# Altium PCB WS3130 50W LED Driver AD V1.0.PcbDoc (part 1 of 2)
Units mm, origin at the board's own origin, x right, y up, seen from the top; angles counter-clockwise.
Board outline 122.48 x 39.96 mm, 2 copper layers (Top Layer, Bottom Layer); 58 components, 32 nets, 164 pads, 32 vias.
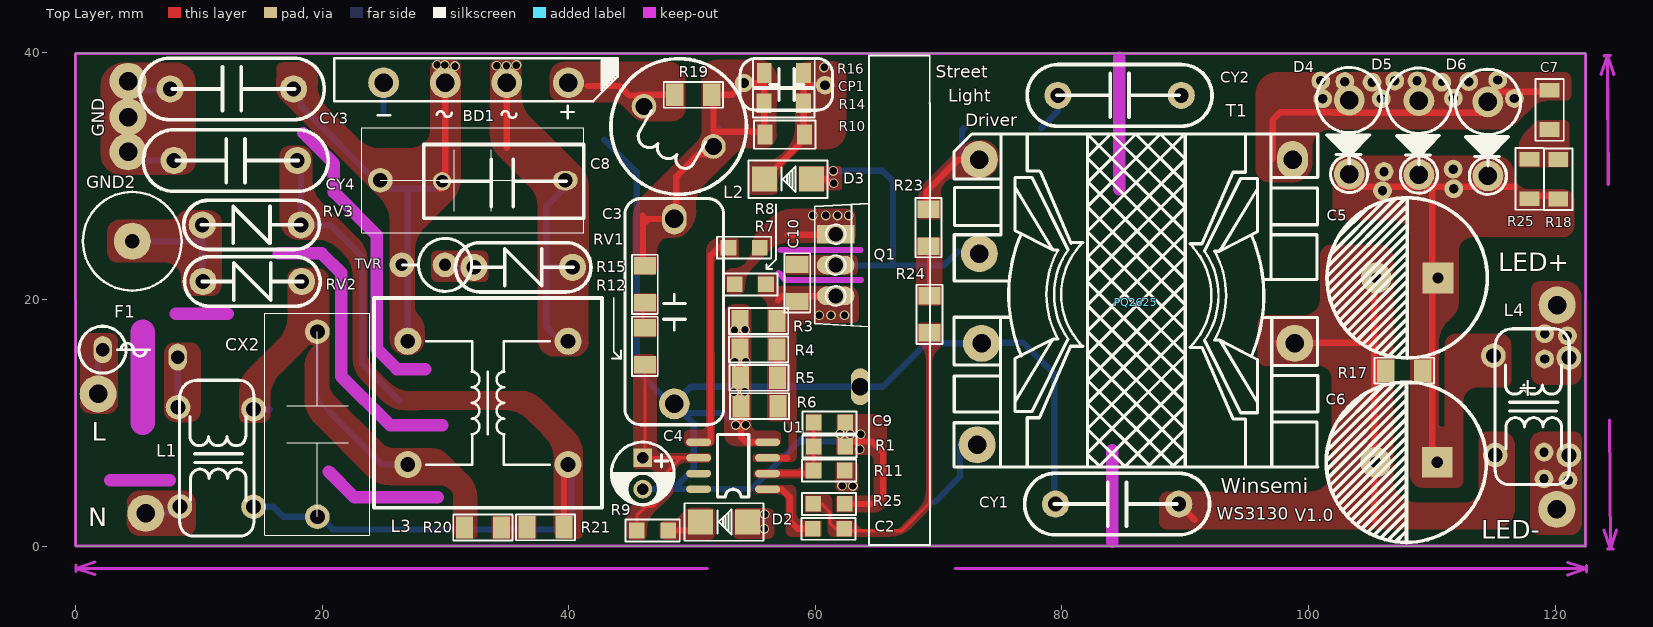
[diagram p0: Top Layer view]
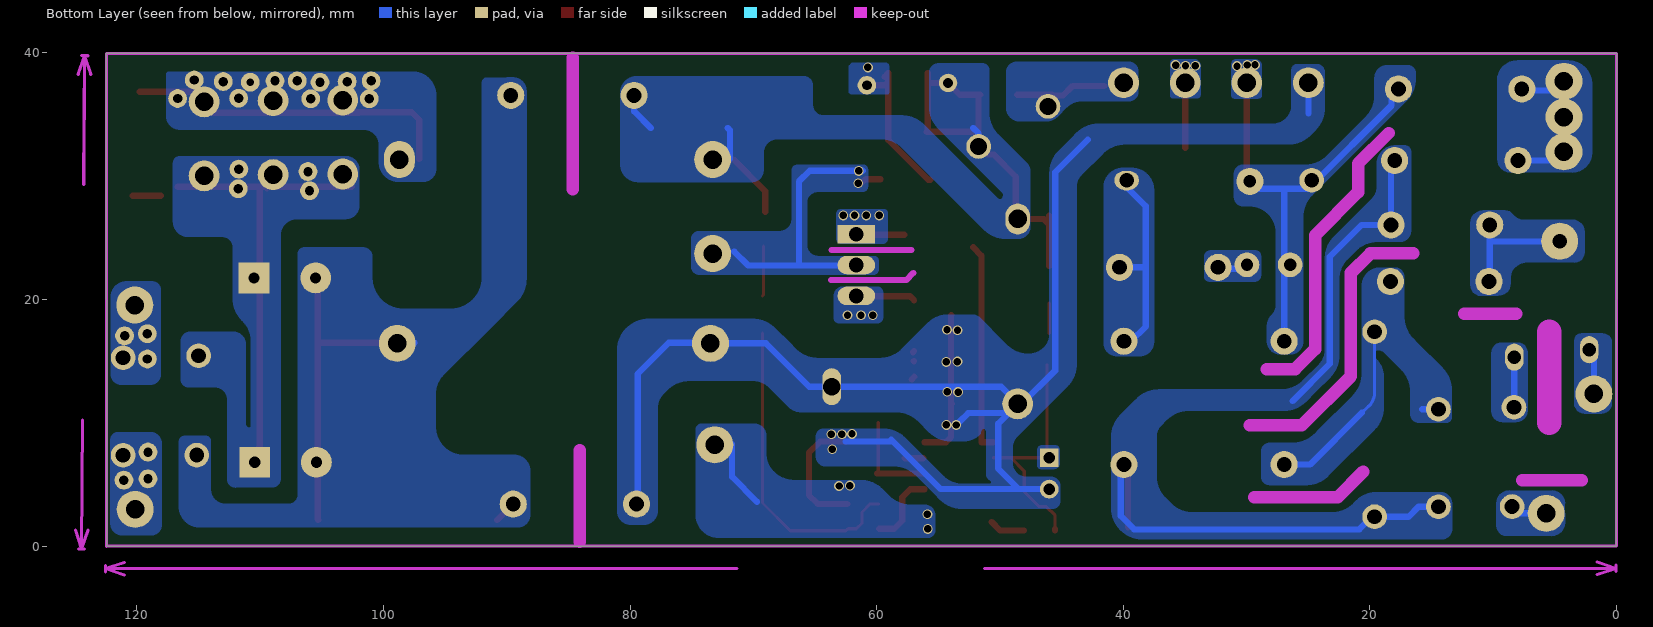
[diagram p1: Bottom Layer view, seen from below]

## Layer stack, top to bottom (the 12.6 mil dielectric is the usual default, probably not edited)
Top Layer: signal copper 0.0356
Dielectric: dielectric 0.32, FR-4, Dk 4.8
Bottom Layer: signal copper 0.0356

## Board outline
-0.011,39.954 0,0 122.439,0 122.472,39.96 -0.011,39.954

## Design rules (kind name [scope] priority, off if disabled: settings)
AcuteAngle [All] p1: minimum=1.50000000000000E+0001
Clearance Clearance_1 [All] p1 off: gap=0.254
Clearance [All] p2 off: gap=0.05
FanoutControl Fanout_Small [All] p1 off: bgadir=Out bgaviamode=Centered fanoutstyle=Auto fanoutdirection=Alternating viagrid=0.025 // Protel DXP Scope 1 Expression Was: (CompPinCount < 5)   Fanout_Small (Default Rule)
FanoutControl Fanout_Default [All] p2: bgadir=Out bgaviamode=Centered fanoutstyle=Auto fanoutdirection=Alternating viagrid=0.025 // Fanout_Default (Default Rule)
FanoutControl Fanout_SOIC [All] p3 off: bgadir=Out bgaviamode=Centered fanoutstyle=Auto fanoutdirection=Alternating viagrid=0.025 // Protel DXP Scope 1 Expression Was: IsSOIC   Fanout_SOIC (Default Rule)
FanoutControl Fanout_BGA [All] p4 off: bgadir=Out bgaviamode=Centered fanoutstyle=Auto fanoutdirection=Alternating viagrid=0.025 // Protel DXP Scope 1 Expression Was: IsBGA   Fanout_BGA (Default Rule)
FanoutControl Fanout_LCC [All] p5 off: bgadir=Out bgaviamode=Centered fanoutstyle=Auto fanoutdirection=Alternating viagrid=0.025 // Protel DXP Scope 1 Expression Was: IsLCC   Fanout_LCC (Default Rule)
PlaneClearance [All] p1: clearance=0.3
PolygonConnect PolygonConnect_1 [All] p1: connectstyle=Direct reliefconductorwidth=0.254 reliefentries=4 polygonreliefangle="90 Angle"
RoutingLayers [All] p1: top layer_v5=FALSE bottom layer_v5=FALSE
RoutingPriority [All] p1: routingpriority=2
RoutingVias [All] p1: holewidth=0.711 width=1.27 viastyle="Through Hole" minholewidth=0.711 minwidth=1.27 maxholewidth=0.711 maxwidth=1.27
SilkscreenOverComponentPads [All] p1: minsilkscreentomaskgap=0.254
SolderMaskExpansion [All] p1: expansion=0.102
TestPointUsage FabricationTestPointUsage [All] p1: valid=0 allowmultiple=FALSE
Testpoint FabricationTestpoint [All] p1: side=3 testpointundercomponent=TRUE minsize=1.016 maxsize=2.54 preferedsize=1.524 minholesize=0 maxholesize=1.016 preferedholesize=0.813 testpointgrid=0.025 style=297 order=0123456789
Width [All] p1: maxlimit=2 minlimit=0.15 preferedwidth=0.3
15 further rules are at their usual default settings.

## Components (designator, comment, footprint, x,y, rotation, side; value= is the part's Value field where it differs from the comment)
BD1 "GBU 606 6A 600V" BD_GBU4J 39.982,37.581 r180 top
C2 "0805" 0805 61.071,1.401 r0 top
C3 "684 450V" CBB18*8_P15 48.568,19.029 r270 top
C4 "CAP100" CAP100 46.009,7.162 r0 top
C5 "CAP_D13H20_T" CAP_D13H20_T 108.003,21.749 r180 top
C6 "CAP_D13H20_T" CAP_D13H20_T 107.943,6.797 r180 top
C7 "Comment" 1206-A 119.553,35.375 r270 top
C8 "CBB6-13" CBB6-13 34.733,29.578 r0 top
C9 "0805" 0805 61.148,10.021 r180 top
C10 "1206" 1206 58.541,21.346 r270 top
CP1 "" CM5A 55.172,37.446 r0 top
CX2 "CAP" X0.33UF/P15#1 19.616,2.385 r270 top
CY1 "CY5-10" CY5-10 84.48,3.407 r0 top
CY2 "CY5-10" CY5-10 84.679,36.553 r0 top
CY3 "CY5-10" CY5-10 12.678,37.075 r180 top
CY4 "CY5-10" CY5-10 12.99,31.27 r180 top
D2 "1N5819" 1N5819 52.591,1.952 r180 top
D3 "1N5819" 1N5819 57.785,29.755 r180 top
D4 "Comment" DK201/P6.0_2 103.303,33.175 r0 top
D5 "Comment" DK201/P6.0_2 108.953,33.125 r0 top
D6 "Comment" DK201/P6.0_2 114.553,33.025 r0 top
F1 "3.15A/250VAC" FUSE-4X8.5 2.205,15.924 r0 top
L1 "Comment" CM5*4 11.671,6.774 r0 top
L2 "" L-DIP10/5A 46.108,35.66 r330 top
L3 "" CM_UU10.5 39.953,16.613 r180 top
L4 "Comment" CM5*4 118.354,10.949 r0 top
PQ2625 "T1" TR-PQ26 73.312,31.351 r0 top
Q1 "Comment" TO-220 61.655,22.792 r0 top
R1 "0805" 0805 61.148,8.079 r0 top
R3 "1206" 1206 55.403,18.25 r180 top
R4 "1206" 1206 55.403,15.95 r180 top
R5 "1206" 1206 55.428,13.65 r180 top
R6 "1206" 1206 55.469,11.346 r180 top
R7 "0805" 0805 54.733,21.225 r0 top
R8 "0805" 0805 54.228,24.2 r180 top
R9 "0805" 0805 46.802,1.257 r0 top
R10 "Comment" 1206-A 57.52,33.377 r0 top
R11 "0805" 0805 61.128,6.125 r180 top
R12 "1206" 1206 46.179,16.205 r90 top
R14 "Comment" 1206-A 57.438,35.908 r180 top
R15 "1206" 1206 46.179,21.226 r270 top
R16 "Comment" 1206-A 57.454,38.372 r180 top
R17 "1206" 1206 107.768,14.224 r0 top
R18 "Comment" 1206-A 117.928,29.775 r90 top
R19 "1206" 1206 50.11,36.603 r0 top
R20 "1206" 1206 33.04,1.511 r0 top
R21 "1206" 1206 38.118,1.525 r0 top
R23 "1206" 1206 69.186,25.824 r90 top
R24 "1206" 1206 69.263,18.796 r90 top
R25 "0805" 0805 61.11,3.42 r0 top
R25 "Comment" 1206-A 120.253,29.75 r270 top
RV1 "ZV8" ZV8 36.31,22.608 r0 top
RV2 "ZV8" ZV8 14.338,21.46 r0 top
RV3 "ZV8" ZV8 14.281,26.05 r0 top
TVR "0.82 1%" R1W 29.971,22.808 r180 top
U1 "Comment" LZC811B 56.131,4.615 r180 top
? "CAP" X0.33UF/P15#2 39.724,29.664 r0 top
? "600M" FDG144_1 4.603,24.725 r90 top

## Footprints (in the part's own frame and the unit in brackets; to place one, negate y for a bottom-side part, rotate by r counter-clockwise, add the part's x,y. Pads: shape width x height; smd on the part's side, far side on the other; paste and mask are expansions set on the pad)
1N5819 [mil]
  rect 80x80 smd: 1(-75,0) 2(75,0)
  silkscreen extent -126,-60 126,60
0805 [mm]
  rect 1.27x1.27 smd: 1(-1.27,0) 2(1.27,0)
  silkscreen extent -2.2,-0.89 2.2,0.89
1206 [mm]
  rect 1.4x1.8 smd: 1(-1.5,0) 2(1.5,0)
  silkscreen extent -2.4,-1.05 2.4,1.05
1206-A [mm]
  rect 1.2x1.6 smd: 1(-1.6,0) 2(1.6,0)
  silkscreen extent -2.5,-1.15 2.5,1.15
BD_GBU4J [mm]
  round 2.5 hole 1.5: 1(0,0) 2(5,0) 3(10,0) 4(15,0)
  silkscreen extent -4,-2 19,2.88
CAP100 [mil]
  rect 60x60 hole 37: 1(0,0)
  round 60 hole 37: 2(0,-100)
  silkscreen extent -100,-150 100,50
CAP_D13H20_T [mm]
  rect 2.5x2.5 hole 0.9: 1(-2.5,0)
  round 2.5 hole 0.9: 2(2.5,0)
  silkscreen extent -6.5,-6.5 6.5,6.5
CBB6-13 [mm]
  round 1.5 / inner round 2.2 / far side round 2.2 hole 1: 1(-5,0)
  round 1.5 hole 1: 2(5,0)
  silkscreen extent -6.5,-3 6.5,3
CBB18*8_P15 [mm]
  oval 2.5x2 hole 1.5: 1(-7.5,0)
  round 2.5 hole 1.5: 2(7.5,0)
  silkscreen extent -9.15,-4 9.19,4
CM5*4 [mm]
  round 2 hole 1.2: 1(2.769,-3.581) 2(-3.203,-3.57) 3(2.769,4.319) 4(-3.356,4.482)
  silkscreen extent -3.22,-5.96 2.79,6.68
CM5A [mm]
  round 1.5 hole 0.8: 1(-0.959,0.116) 2(5.624,-0.066)
  silkscreen extent -1.26,-2.1 6.24,2.1
CM_UU10.5 [mm]
  round 2.2 hole 1.2: 1(0,0) 2(0,10) 3(13,0) 4(13,10)
  silkscreen extent -2.75,-3.5 15.75,13.5
CY5-10 [mm]
  round 2.2 hole 1.2: 1(-5,0) 2(5,0)
  silkscreen extent -7.5,-2.5 7.5,2.5
DK201/P6.0_2 [mm]
  round 2.5 hole 1.5: A(0,3) K(0,-3)
  silkscreen extent -2.65,-4.51 2.65,5.65
FDG144_1 [mm]
  round 3 hole 1.2: 1(0,0)
  silkscreen extent -4,-4 4,4
FUSE-4X8.5 [mm]
  oval 1.5x2.2 hole 1.1: 1(0,0) 2(6.081,-0.602)
  silkscreen extent -1.92,-1.9 3.8,1.9
L-DIP10/5A [mm]
  round 2 hole 1.4: 1(0,0) 2(6.5,0)
  silkscreen extent -2.25,-5.5 8.75,5.5
LZC811B [mil]
  oval 80x24 smd: CMP(0,0) CS(0,-100) DRV(220,-150) FB(0,-50) GND(0,-150) NC(220,-50) NC(220,0) VDD(220,-100)
  silkscreen extent 60,-175 160,25
R1W [mm]
  round 2 hole 1: 1(0,0) 2(3.5,0)
  silkscreen extent -2.15,-2.15 3.46,2.15
TO-220 [mm]
  rect 3.048x1.5 hole 1.2: 1(0,2.5)
  oval 3.048x1.5 hole 1.2: 2(0,0) 3(0,-2.5)
  silkscreen extent -1.7,-5 2.7,5
TR-PQ26 [mm]
  round 3 hole 1.5: 1(-0.003,0.001) 3(-0.003,-7.624) 4(0.172,-14.912) 6(-0.178,-23.136) 9(25.575,-14.908)
  oval 2.5x3 hole 1.5: 12(25.397,0.001)
  silkscreen extent -2.06,-24.92 27.44,2.08
X0.33UF/P15#1 [mm]
  round 2 hole 1.2: 1(0,0) 2(-15,0)
  silkscreen extent -16.5,-4.25 1.5,4.25
X0.33UF/P15#2 [mm]
  oval 2x1.5 hole 1.2: 1(0,0)
  round 2 hole 1.2: 2(-15,0)
  silkscreen extent -16.5,-4.25 1.5,4.25
ZV8 [mm]
  round 2.2 hole 1.2: 1(-4,0) 2(4,0)
  silkscreen extent -5.5,-2 5.5,2

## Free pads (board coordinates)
  round 3 hole 1.5: 0(5.705,2.658) 1(1.832,12.339) 1(4.259,31.975) 1(4.259,34.8) 1(4.259,37.7) 1(120.14,2.977) 1(120.173,19.55)
  round 1.524 hole 0.6: 0(110.803,37.625)
  oval 1.524x3 hole 1.4: 1(63.648,12.925)
  round 1.524 hole 0.762: 1(113.003,37.675) 2(108.803,37.725) 3(107.003,37.725) 4(105.153,37.625) 5(102.953,37.675) 6(101.003,37.725) 7(101.153,36.275) 8(105.903,36.275) 9(111.753,36.325) 10(115.353,37.8) 11(116.703,36.3) 12(106.128,30.375) 13(111.728,30.575) 14(106.003,28.825) 15(111.778,28.975) 16(121.003,17.05) 17(119.153,17.225) 18(119.153,15.175) 19(121.053,5.35) 20(119.103,5.45) 21(119.103,7.625)

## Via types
v1: diameter 0.8, hole 0.6, Top Layer to Bottom Layer, 32 vias

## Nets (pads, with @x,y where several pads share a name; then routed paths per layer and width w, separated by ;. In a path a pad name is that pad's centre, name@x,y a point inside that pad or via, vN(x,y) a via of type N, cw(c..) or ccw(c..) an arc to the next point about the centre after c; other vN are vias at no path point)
CMP: C2.1 U1.CMP | length 6.1
  Top Layer w0.508: U1.CMP@56.131,4.615 57.274,4.615 57.926,3.963 57.926,2.061 58.586,1.401 C2.1@59.801,1.401
cs: C10.2 Q1.3 R3.1 R4.1 R5.1 R6.1 R7.2 U1.CS | length 6.6
  Top Layer w0.508: U1.CS@56.23,7.129 57.735,7.129 ; R5.1@56.953,13.728 R5.1@57.168,13.513 ; 56.969,14.969 57.002,15.002 ; R4.1@56.969,15.795 R4.1@57.052,15.713 ; 56.969,19.925 57.303,20.259 Q1.3@61.457,20.259
  other v1: 60.315,18.725 61.275,18.725 62.366,18.725
DRV: R8.2 U1.DRV | length 17
  Top Layer w0.508: U1.DRV@50.543,8.425 51.506,8.425 51.506,23.559 52.178,24.231
FB: C9.2 R1.1 R11.2 U1.FB | length 8
  Top Layer w0.254: R11.2@59.839,5.885 ccw(c59.839,5.923) 59.878,5.923 C9.2@59.878,10.021
  Top Layer w0.508: U1.FB@56.131,5.885 R11.2@59.975,5.885
G: Q1.1 R7.1 R8.1 | length 3.7
  Top Layer w0.508: 57.771,25.259 Q1.1@61.457,25.259
  other v1: 59.794,26.825 60.853,26.825 61.804,26.825 62.714,26.825
GND: C5.2 C6.2 CY1.2 CY2.2 L4.2 PQ2625.9 R17.1 | length 29.2
  Top Layer w0.508: CY1.2@89.48,3.407 90.77,2.117 ; PQ2625.9@97.485,16.485 104.968,16.485 104.989,16.507 105.334,16.507 ; C5.2@104.989,21.006 105.334,20.661 105.334,2.164 105.287,2.117
  Bottom Layer w0.508: PQ2625.9@97.485,16.485 PQ2625.9@97.81,16.159
gnd1: CY3.2 CY4.2 pad.1@4.259,31.975 pad.1@4.259,34.8 pad.1@4.259,37.7 | length 13.8
  Bottom Layer w0.508: pad.1@4.213,38.068 4.242,38.04 4.242,31.643 4.615,31.27 CY4.2@7.99,31.27 ; pad.1@4.242,36.921 4.27,36.95 CY3.2@7.646,36.95
GND2: ?.1@4.603,24.725 RV2.1 RV3.1 | length 10.6
  Bottom Layer w0.508: ?.1@4.27,24.702 10.224,24.702 10.281,24.759 ; RV3.1@10.281,26.05 10.281,21.518 RV2.1@10.338,21.46
GNDE: BD1.4 C3.2 C4.2 C9.1 CY1.1 pad.1@63.648,12.925 PQ2625.4 R1.2 R3.2 R4.2 R5.2 R6.2 R25.2@62.38,3.42 U1.GND | length 125.7
  Top Layer w0.508: R6.2@53.912,11.554 R6.2@53.969,11.611 ; R3.2@53.953,18.723 53.969,18.707 53.969,16.209 R6.2@53.969,11.611 ; U1.GND@56.131,8.425 54.388,8.425 53.969,8.844 R6.2@53.969,11.346 R6.2@53.969,11.611 ; R25.2@62.38,3.42 64.798,3.42 65.497,4.119 65.497,7.575 64.593,8.478 R1.2@62.517,8.478
  Bottom Layer w0.508: 24.982,35.112 BD1.4@24.982,37.581 ; 42.879,32.963 45.512,30.329 45.512,14.224 ; 45.539,14.214 C3.2@48.384,11.369 ; C4.2@46.009,4.622 54.798,4.622 58.81,8.634 ; C3.2@48.357,11.379 49.903,12.925 65.466,12.925 68.985,16.444 PQ2625.4@72.939,16.444 ; 48.48,4.622 50.143,6.285 50.143,9.933 C3.2@49.292,10.784 ; C3.2@48.556,11.521 C3.2@49.292,10.784 ; v1@53.286,10.089 52.591,10.784 C3.2@49.292,10.784 ; 58.733,8.478 62.517,8.478 ; PQ2625.4@72.081,16.481 76.865,16.481 79.386,13.96 CY1.1@79.386,2.911
  other v1: 63.603,7.85 62.828,9.075 63.678,9.075 62.003,9.1 53.551,9.816 54.345,9.825 53.394,12.488 54.278,12.521 54.361,14.944 53.46,14.96 53.451,17.507 54.295,17.549
HV: 
HV1: CP1.2 D3.2 R10.2 R14.1 R16.1 | length 12
  Top Layer w0.508: D3.2@55.665,29.705 55.817,29.705 59.054,32.943 R16.1@59.054,38.372 R16.1@59.359,38.067 ; 59.359,37.413 59.392,37.38 CP1.2@60.795,37.38
  other v1: 60.712,38.825
L: F1.1 pad.1@1.832,12.339 | length 3.7
  Bottom Layer w0.508: pad.1@1.832,12.339 1.832,15.551 F1.1@2.205,15.924
L0: F1.2 L1.4 | length 4.1
  Bottom Layer w0.508: F1.2@8.286,15.322 8.286,11.285 L1.4@8.315,11.256
L1: CX2.1 CY4.1 L1.1 L3.2 R21.2 RV3.2 | length 60.5
  Top Layer w0.508: R21.2@39.618,1.525 39.618,6.019 L3.2@40.211,6.613
  Bottom Layer w0.508: L1.1@14.439,3.193 16.055,3.193 16.863,2.385 19.817,2.385 20.85,1.353 39.121,1.353 40.211,2.443 L3.2@40.211,6.613 ; CY4.1@18.334,31.012 18.281,30.959 RV3.2@18.281,26.05 20.678,26.05 23.259,23.468 23.259,14.777 26.271,11.765
L2: ?.1@39.724,29.664 BD1.2 C8.2 L3.1 RV1.2 | length 21.6
  Top Layer w0.508: 34.982,32.3 BD1.2@34.982,37.581
  Bottom Layer w0.508: 38.231,22.608 RV1.2@40.31,22.608 ; C8.2@39.589,28.976 38.188,27.574 38.188,17.805 39.38,16.613 L3.1@40.211,16.613
  other v1: 34.159,38.953 34.959,38.953 35.759,39.004
LED+: L4.3 pad.1@120.173,19.55 pad.16 pad.17 pad.18
LED-: L4.1 pad.1@120.14,2.977 pad.19 pad.20 pad.21
N: CX2.2 L1.3 L3.4 R20.1 RV2.2 | length 17.1
  Top Layer w0.508: L3.4@26.621,6.022 L3.4@27.211,6.613
  Bottom Layer w0.254: CX2.2@19.616,17.385 19.616,12.465 ccw(c21.193,12.465) 20.078,11.35 cw(c20.078,11.255) 20.145,11.322 20.663,10.804
  Bottom Layer w0.508: L1.3@14.439,11.093 15.76,11.093 ; 20.663,10.804 24.855,6.613 L3.4@26.953,6.613
N0: L1.2 pad.0@5.705,2.658 | length 3
  Bottom Layer w0.508: pad.0@5.705,2.658 7.922,2.658 L1.2@8.468,3.204
N1: ?.2 BD1.3 C8.1 CY3.1 L3.3 TVR.2 | length 36.4
  Top Layer w0.508: C8.1@29.589,28.976 29.982,29.368 BD1.3@29.982,37.581
  Bottom Layer w0.508: CY3.1@18.248,36.806 18.248,35.736 24.753,29.232 24.753,28.976 29.283,28.976 C8.1@29.398,29.09 ; L3.3@26.953,16.613 26.953,28.969 26.959,28.976
  other v1: 30.78,38.925 29.316,39.025 29.947,39.022
n3: R20.2 R21.1
N4: RV1.1 TVR.1 | length 2.3
  Bottom Layer w0.508: TVR.1@29.982,22.493 RV1.1@32.253,22.493
ST: R12.2 R15.2
TA: D2.1 PQ2625.6 R11.1 | length 5.5
  Bottom Layer w0.508: 69.718,3.597 71.731,5.611 PQ2625.6@71.731,8.256
  other v1: 55.858,1.398 55.891,2.58 63.053,4.875 62.178,4.9
TA1: D2.2 R9.2 | length 2.9
  Top Layer w0.508: R9.2@48.072,1.257 49.992,1.257 D2.2@50.686,1.952
TS: C7.1 D4.A D5.A D6.A pad.0@110.803,37.625 pad.1@113.003,37.675 pad.2 pad.3 pad.4 pad.5 pad.6 pad.7 pad.8 pad.9 pad.10 pad.11 PQ2625.12 | length 28
  Top Layer w0.508: 97.108,31.394 97.108,34.576 97.718,35.186 D4.A@102.542,35.186 ; 101.967,35.136 114.642,35.136 115.099,35.593 115.099,36.602 115.343,36.846 C7.1@119.763,36.846
TS1: C7.2 R18.2 R25.1@120.253,31.35
VBUS: C3.1 CP1.1 CY2.1 L2.2 PQ2625.1 R10.1 R14.2 R15.1 R16.2 R19.2 R23.2 | length 46.8
  Top Layer w0.508: R15.1@46.005,22.721 46.005,26.794 ; 46.03,26.105 46.455,26.53 C3.1@48.721,26.53 ; C3.1@48.953,26.554 48.929,26.53 C3.1@48.721,26.53 ; 51.979,33.592 51.996,33.609 55.953,33.609 55.854,33.708 R16.2@55.854,37.578 ; R16.2@55.854,38.372 R16.2@55.854,37.578 ; R23.2@69.031,27.105 69.031,28.775 71.608,31.352 PQ2625.1@73.308,31.352 ; C3.1@48.721,26.53 48.721,29.97 50.507,31.756 51.084,31.756 L2.2@51.737,32.41 51.737,36.476 R19.2@51.61,36.603 53.253,36.603 CP1.1@54.212,37.562 55.838,37.562 R16.2@55.854,37.578
  Bottom Layer w0.508: L2.2@51.737,32.41 51.737,33.466 52.178,33.907 ; PQ2625.1@71.906,31.394 71.906,33.738 72.075,33.907 ; 78.327,33.907 79.679,35.258 CY2.1@79.679,36.553
VBUS1: BD1.1 L2.1 R19.1 | length 8.4
  Top Layer w0.508: 41.52,37.314 44.123,37.314 44.9,36.536 45.711,36.536 45.777,36.603 ; L2.1@45.893,35.693 45.893,36.487 45.777,36.603 ; R19.1@48.61,36.603 45.777,36.603
VDD: C4.1 R9.1 R12.1 U1.VDD | length 21.4
  Top Layer w0.254: R9.1@45.532,1.257 45.532,2.494 46.239,3.2 46.822,3.2 48.031,4.409 48.031,6.076 49.11,7.155 U1.VDD@50.543,7.155 50.536,7.162 C4.1@46.009,7.162 46.179,7.332 R12.1@46.179,14.705
  Top Layer w0.508: R9.1@45.532,1.257 R9.1@45.532,1.393
VDS: C10.1 D3.1 PQ2625.3 Q1.2 | length 24.6
  Top Layer w0.508: D3.1@59.69,29.755 60.911,29.755 v1@61.209,29.457
  Bottom Layer w0.508: v1@61.126,30.45 65.426,30.45 66.303,29.573 66.303,22.792 66.336,22.759 ; Q1.2@61.457,22.759 70.421,22.759 71.546,23.883
  other v1: 61.495,29.425 61.457,30.425
VOUT: C5.1 C6.1 D4.K D5.K D6.K L4.4 pad.12 pad.13 pad.14 pad.15 R17.2 R18.1 R25.2@120.253,28.15 | length 38.1
  Top Layer w0.508: 102.578,29.136 116.71,29.136 ; D5.K@109.462,29.023 D5.K@109.575,29.136 ; 110.037,29.073 110.037,8.052 C6.1@110.381,7.708 ; R18.1@118.068,28.403 R25.2@120.338,28.403
pads on no net: C2.2 R23.1 R24.1 R24.2 R25.1@59.84,3.42 U1.NC
copper on no net: | length 32.1
  Top Layer w0.254: 45.986,17.228 46.005,17.248 46.005,19.721 ; 59.84,3.42 60.527,3.42 61.187,2.76 61.187,1.867 61.653,1.401 62.341,1.401 62.496,1.245 67.011,1.245 69.263,3.498 69.263,17.296 ; 69.186,24.324 69.186,20.374 69.263,20.296

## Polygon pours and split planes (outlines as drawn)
TA on Top Layer "Top Layer-No Net" (solid, remove dead copper, pour order 1001): 62.228,6.8 61.803,6.8 ccw(c61.803,6.675) 61.678,6.675 61.678,4.725 ccw(c61.953,4.725) 61.953,4.45 63.203,4.45 ccw(c63.203,4.725) 63.478,4.725 63.478,6.5 ccw(c63.178,6.5) 63.178,6.8 62.228,6.8
N4 on Top Layer "Top Layer-No Net" (solid, remove dead copper, pour order 1000): 32.078,23.95 29.303,23.95 ccw(c29.303,23.5) 28.853,23.5 28.853,21.95 ccw(c29.378,21.95) 29.378,21.425 33.028,21.425 ccw(c33.028,21.875) 33.478,21.875 33.478,23.425 ccw(c32.953,23.425) 32.953,23.95 32.078,23.95
GNDE on Top Layer "Top Layer-GNDE 2" (solid, remove dead copper, pour order 1045): 62.153,10.7 61.853,10.7 ccw(c61.853,10.575) 61.728,10.575 61.728,7.525 ccw(c61.853,7.525) 61.853,7.4 64.303,7.4 cw(c64.303,6.975) 64.728,6.975 64.728,4.375 cw(c64.428,4.375) 64.428,4.075 61.853,4.075 ccw(c61.853,3.9) 61.678,3.9 61.678,2.875 ccw(c61.828,2.875) 61.828,2.725 64.753,2.725 ccw(c64.753,3.775) 65.803,3.775 65.803,9.7 ccw(c64.803,9.7) 64.803,10.7 62.153,10.7
no net on Top Layer "Top Layer-No Net 1" (solid, pour order 1044): 69.153,25.05 68.378,25.05 ccw(c68.378,24.875) 68.203,24.875 68.203,19.775 ccw(c68.478,19.775) 68.478,19.5 69.978,19.5 ccw(c69.978,19.8) 70.278,19.8 70.278,24.7 ccw(c69.928,24.7) 69.928,25.05 69.153,25.05
VBUS on Top Layer "Top Layer-VBUS 5" (solid, remove dead copper, pour order 1043): 73.553,32.9 73.283,32.9 ccw(c73.283,30.595) 71.653,32.225 69.003,29.575 ccw(c70.753,27.825) 68.278,27.825 68.278,26.75 ccw(c68.528,26.75) 68.528,26.5 69.953,26.5 ccw(c69.953,26.75) 70.203,26.75 70.203,28.65 cw(c71.403,28.65) 71.403,29.85 73.403,29.85 ccw(c73.403,31.325) 74.878,31.325 74.878,31.575 ccw(c73.553,31.575) 73.553,32.9
no net on Top Layer "Top Layer-No Net" (solid, pour order 1042): 59.903,4.175 59.328,4.175 ccw(c59.328,4) 59.153,4 59.153,2.875 ccw(c59.328,2.875) 59.328,2.7 60.578,2.7 cw(c60.578,2.25) 61.028,2.25 61.028,1.2 ccw(c61.453,1.2) 61.453,0.775 66.026,0.775 ccw(c66.026,3.315) 67.822,1.519 69.253,2.95 cw(c69.253,2.95) 69.253,2.95 ccw(c68.649,3.554) 69.503,3.554 69.503,4.975 69.503,14.92 cw(c70.783,14.92) 69.878,15.825 ccw(c68.912,16.791) 70.278,16.791 70.278,16.975 70.278,17.85 ccw(c70.003,17.85) 70.003,18.125 68.503,18.125 ccw(c68.503,17.9) 68.278,17.9 68.278,16.772 ccw(c68.876,16.772) 68.453,16.35 cw(c67.125,15.022) 69.003,15.022 69.003,13.9 69.003,4.702 cw(c66.463,4.702) 68.259,2.906 66.878,1.525 cw(c66.516,1.887) 66.516,1.375 63.903,1.375 cw(c63.903,1.677) 63.69,1.463 63.253,1.9 ccw(c62.71,1.357) 62.71,2.125 62.703,2.125 61.728,2.125 cw(c61.728,2.475) 61.378,2.475 61.378,3.7 ccw(c60.903,3.7) 60.903,4.175 59.903,4.175
CMP on Top Layer "Top Layer-CMP 1" (solid, remove dead copper, pour order 1041): 56.403,4.95 55.328,4.95 ccw(c55.328,4.725) 55.103,4.725 55.103,4.45 ccw(c55.353,4.45) 55.353,4.2 56.978,4.2 cw(c56.978,3.575) 57.603,3.575 57.603,1.275 ccw(c58.103,1.275) 58.103,0.775 60.378,0.775 ccw(c60.378,0.925) 60.528,0.925 60.528,1.9 ccw(c60.353,1.9) 60.353,2.075 59.028,2.075 cw(c59.028,2.65) 58.453,2.65 58.453,4.5 ccw(c58.003,4.5) 58.003,4.95 56.403,4.95
FB on Top Layer "Top Layer-FB 1" (solid, remove dead copper, pour order 1040): 59.553,10.725 59.403,10.725 ccw(c59.403,10.5) 59.178,10.5 59.178,7.125 cw(c58.278,7.125) 58.278,6.225 55.353,6.225 ccw(c55.353,5.875) 55.003,5.875 ccw(c55.378,5.875) 55.378,5.5 60.353,5.5 ccw(c60.353,5.675) 60.528,5.675 60.528,10.625 ccw(c60.428,10.625) 60.428,10.725 59.553,10.725
G on Top Layer "Top Layer-G" (solid, remove dead copper, pour order 1039): 62.003,27.35 58.18,27.35 ccw(c58.18,24.81) 56.384,26.606 56.003,26.225 55.647,25.869 55.324,25.546 ccw(c56.221,24.65) 54.953,24.65 54.953,24.615 cw(c52.563,24.615) 54.253,22.925 cw(c53.348,23.83) 53.348,22.55 53.328,22.55 ccw(c53.328,21.925) 52.703,21.925 52.703,21.9 52.703,20.875 ccw(c53.153,20.875) 53.153,20.425 53.778,20.425 ccw(c53.778,20.925) 54.278,20.925 cw(c56.753,20.925) 55.003,22.675 55.778,23.45 56.274,23.946 cw(c57.853,22.367) 57.853,24.6 62.703,24.6 ccw(c62.703,25.175) 63.278,25.175 63.278,26.675 ccw(c62.603,26.675) 62.603,27.35 62.003,27.35
cs on Top Layer "Top Layer-cs" (solid, remove dead copper, pour order 1038): 55.303,21.1 55.303,20.749 ccw(c55.844,20.749) 55.462,20.366 55.928,19.9 cw(c55.506,19.478) 56.103,19.478 56.103,18.725 56.103,10.5 ccw(c56.503,10.5) 56.503,10.1 57.328,10.1 cw(c57.328,9.575) 57.853,9.575 57.853,7.975 cw(c57.353,7.975) 57.353,7.475 55.178,7.475 ccw(c55.178,7.225) 54.928,7.225 54.928,7.025 ccw(c55.128,7.025) 55.128,6.825 58.053,6.825 ccw(c58.053,7.25) 58.478,7.25 58.478,17.05 cw(c59.528,17.05) 59.528,18.1 63.103,18.1 ccw(c63.103,18.525) 63.528,18.525 63.528,20.175 ccw(c62.603,20.175) 62.603,21.1 57.203,21.1 cw(c57.203,21.5) 56.803,21.5 56.803,21.8 ccw(c56.553,21.8) 56.553,22.05 55.603,22.05 ccw(c55.603,21.75) 55.303,21.75 55.303,21.1
GNDE on Top Layer "Top Layer-GNDE 1" (solid, remove dead copper, pour order 1037): 53.578,19.6 53.378,19.6 ccw(c53.378,18.85) 52.628,18.85 52.628,9.025 ccw(c53.553,9.025) 53.553,8.1 56.778,8.1 ccw(c56.778,8.525) 57.203,8.525 57.203,8.95 ccw(c56.803,8.95) 56.803,9.35 55.328,9.35 cw(c55.328,9.875) 54.803,9.875 54.803,19 ccw(c54.203,19) 54.203,19.6 53.578,19.6
VDS on Top Layer "Top Layer-VDS 2" (solid, remove dead copper, pour order 1036): 63.003,23.6 57.828,23.6 ccw(c57.828,23.325) 57.553,23.325 57.553,22.275 ccw(c57.828,22.275) 57.828,22 63.078,22 ccw(c63.078,22.35) 63.428,22.35 63.428,23.175 ccw(c63.003,23.175) 63.003,23.6
TA on Top Layer "Top Layer-TA 1" (solid, remove dead copper, pour order 1035): 55.478,3.075 53.778,3.075 ccw(c53.778,2.65) 53.353,2.65 53.353,0.95 ccw(c53.703,0.95) 53.703,0.6 56.203,0.6 ccw(c56.203,1.05) 56.653,1.05 56.653,2.575 ccw(c56.153,2.575) 56.153,3.075 55.478,3.075
TA1 on Top Layer "Top Layer-TA1" (solid, remove dead copper, pour order 1034): 47.378,1.65 47.378,0.9 ccw(c47.753,0.9) 47.753,0.525 51.403,0.525 ccw(c51.403,1) 51.878,1 51.878,2.75 ccw(c51.528,2.75) 51.528,3.1 49.971,3.1 ccw(c49.971,2.332) 49.428,2.875 48.939,2.386 cw(c48.128,3.197) 48.128,2.05 47.778,2.05 ccw(c47.778,1.65) 47.378,1.65
DRV on Top Layer "Top Layer-DRV" (solid, remove dead copper, pour order 1033): 53.178,24.975 52.228,24.975 ccw(c52.228,23.9) 51.153,23.9 51.153,9.9 cw(c50.678,9.9) 50.678,9.425 49.753,9.425 ccw(c49.753,9.05) 49.378,9.05 49.378,8.4 ccw(c49.703,8.4) 49.703,8.075 51.303,8.075 ccw(c51.303,8.6) 51.828,8.6 51.828,22.95 cw(c52.178,22.95) 52.178,23.3 53.528,23.3 ccw(c53.528,23.575) 53.803,23.575 53.803,24.725 ccw(c53.553,24.725) 53.553,24.975 53.178,24.975
HV1 on Top Layer "Top Layer-HV1" (solid, remove dead copper, pour order 1032): 60.503,39.325 59.478,39.325 ccw(c59.478,38.2) 58.353,38.2 58.353,38 58.353,33.952 cw(c55.813,33.952) 57.609,32.156 57.528,32.075 57.367,31.914 cw(c55.703,33.579) 55.703,31.225 55.253,31.225 ccw(c55.253,30.5) 54.528,30.5 54.528,28.825 ccw(c54.853,28.825) 54.853,28.5 56.553,28.5 ccw(c56.553,28.925) 56.978,28.925 56.978,29.348 cw(c59.518,29.348) 57.722,31.144 58.603,32.025 cw(c59.026,31.603) 59.026,32.2 61.003,32.2 ccw(c61.003,33.7) 62.503,33.7 62.503,35.525 62.503,38.35 ccw(c61.528,38.35) 61.528,39.325 60.503,39.325
N0 on Top Layer "Top Layer-N0" (solid, remove dead copper, pour order 1031): 5.678,4.5 5.221,4.5 ccw(c5.221,3.457) 4.178,3.457 4.178,1.925 ccw(c5.278,1.925) 5.278,0.825 8.903,0.825 ccw(c8.903,1.675) 9.753,1.675 9.753,3.45 ccw(c8.703,3.45) 8.703,4.5 5.678,4.5
L0 on Top Layer "Top Layer-L0" (solid, remove dead copper, pour order 1030): 8.703,16.5 8.003,16.5 ccw(c8.003,15.7) 7.203,15.7 7.203,11 ccw(c8.153,11) 8.153,10.05 9.259,10.05 ccw(c9.259,10.95) 10.159,10.95 10.159,15.644 ccw(c9.303,15.644) 9.303,16.5 8.703,16.5
L on Top Layer "Top Layer-L" (solid, remove dead copper, pour order 1029): 2.303,17.25 1.103,17.25 ccw(c1.103,16.525) 0.378,16.525 0.378,11.575 ccw(c1.203,11.575) 1.203,10.75 2.603,10.75 ccw(c2.603,11.575) 3.428,11.575 3.428,16.65 ccw(c2.828,16.65) 2.828,17.25 2.303,17.25
GND2 on Top Layer "Top Layer-GND2" (solid, remove dead copper, pour order 1028): 10.378,27.225 9.003,27.225 ccw(c9.003,26.561) 8.534,27.031 8.328,26.825 cw(c7.483,27.67) 7.483,26.475 6.853,26.475 3.603,26.475 ccw(c3.603,25.45) 2.578,25.45 2.578,23.825 ccw(c3.403,23.825) 3.403,23 7.131,23 cw(c7.131,21.378) 8.278,22.525 cw(c7.554,21.801) 8.578,21.801 8.578,21.325 ccw(c9.604,21.325) 9.604,20.299 9.953,20.299 10.957,20.299 ccw(c10.957,21.2) 11.859,21.2 11.859,26.194 ccw(c10.828,26.194) 10.828,27.225 10.378,27.225
gnd1 on Top Layer "Top Layer-gnd1" (solid, remove dead copper, pour order 1027): 5.178,39.212 3.938,39.212 ccw(c3.938,37.325) 2.051,37.325 2.051,31.725 ccw(c3.651,31.725) 3.651,30.125 8.653,30.125 ccw(c8.653,31.225) 9.753,31.225 9.753,37.587 ccw(c8.128,37.587) 8.128,39.212 5.251,39.212
N on Top Layer "Top Layer-N" (solid, remove dead copper, pour order 1026): 13.278,12.269 13.278,10.5 ccw(c13.778,10.5) 13.778,10 15.028,10 ccw(c15.028,10.775) 15.803,10.775 15.803,12.123 cw(c18.343,12.123) 16.547,13.919 18.753,16.125 18.865,16.237 cw(c19.078,16.023) 19.078,16.325 19.168,16.325 cw(c19.168,16.24) 19.228,16.3 cw(c19.168,16.24) 19.253,16.24 19.253,16.2 cw(c19.132,16.2) 19.218,16.115 19.203,16.1 19.151,16.048 ccw(c20.473,14.725) 18.603,14.725 18.603,11.853 ccw(c21.143,11.853) 19.347,10.057 23.769,5.634 ccw(c25.481,7.346) 25.481,4.925 26.878,4.925 29.558,4.925 cw(c29.558,3.73) 30.403,4.575 cw(c29.799,3.971) 30.653,3.971 30.653,2.55 30.653,0.95 ccw(c31.003,0.95) 31.003,0.6 32.303,0.6 ccw(c32.303,0.875) 32.578,0.875 32.578,3.923 ccw(c30.038,3.923) 31.834,5.719 30.103,7.45 ccw(c28.938,6.285) 28.938,7.933 25.89,7.933 cw(c25.89,9.429) 24.832,8.371 20.928,12.275 cw(c21.773,13.12) 20.578,13.12 20.578,19.475 20.578,21.514 ccw(c19.523,21.514) 19.523,22.57 18.086,22.57 18.035,22.57 ccw(c18.035,21.739) 17.205,21.739 17.205,18.554 cw(c14.665,18.554) 16.461,16.758 16.153,16.45 14.022,14.319 ccw(c15.818,12.523) 13.278,12.523 13.278,12.269
n3 on Top Layer "Top Layer-n3" (solid, remove dead copper, pour order 1025): 34.953,2.45 33.953,2.45 ccw(c33.953,2.25) 33.753,2.25 33.753,0.775 ccw(c33.978,0.775) 33.978,0.55 37.128,0.55 ccw(c37.128,0.8) 37.378,0.8 37.378,2.325 ccw(c37.253,2.325) 37.253,2.45 34.903,2.45 cw(c34.903,2.45) 34.903,2.45
L1 on Top Layer "Top Layer-L1" (solid, remove dead copper, pour order 1024): 17.303,32.45 ccw(c17.303,31.725) 16.578,31.725 16.578,31.6 16.578,26.435 ccw(c18.219,26.435) 17.059,25.275 ccw(c18.145,26.361) 18.145,24.825 19.659,24.825 cw(c19.659,22.532) 21.28,24.153 21.459,23.975 21.755,23.679 cw(c19.959,21.882) 22.499,21.882 22.499,21.85 22.499,15.231 ccw(c25.039,15.231) 23.243,13.435 23.478,13.2 24.909,11.769 ccw(c26.705,13.565) 26.705,11.025 27.803,11.025 34.851,11.025 cw(c34.851,8.485) 36.647,10.281 37.553,9.375 38.059,8.869 cw(c36.263,7.073) 38.803,7.073 38.803,3.375 38.803,1.275 ccw(c39.478,1.275) 39.478,0.6 40.778,0.6 ccw(c40.778,0.95) 41.128,0.95 41.128,1.15 41.128,7.525 ccw(c38.653,7.525) 40.403,9.275 37.847,11.831 ccw(c36.051,10.035) 36.051,12.575 35.628,12.575 27.187,12.575 cw(c27.187,15.115) 25.391,13.319 24.159,14.552 cw(c25.379,15.772) 23.653,15.772 23.653,19.875 23.653,23.173 ccw(c21.113,23.173) 22.909,24.969 21.978,25.9 19.944,27.934 cw(c21.74,29.73) 19.2,29.73 19.2,30.775 19.2,31.553 ccw(c18.303,31.553) 18.303,32.45 17.303,32.45
N1 on Top Layer "Top Layer-N1 1" (solid, remove dead copper, pour order 1023): 17.803,39.225 16.853,39.225 ccw(c16.853,38.675) 16.303,38.675 16.303,37.155 ccw(c17.583,37.155) 16.678,36.25 24.734,28.194 cw(c22.938,26.398) 25.478,26.398 25.478,21.525 25.478,16.925 25.478,16.8 ccw(c26.778,16.8) 26.778,15.5 27.003,15.5 ccw(c27.003,16.825) 28.328,16.825 28.328,17.412 ccw(c26.365,17.412) 27.753,18.8 cw(c28.296,19.343) 27.528,19.343 27.528,23.275 27.528,23.998 cw(c30.068,23.998) 28.272,25.794 30.153,27.675 30.484,28.006 ccw(c28.688,29.802) 31.228,29.802 31.228,34 31.228,38.875 ccw(c30.678,38.875) 30.678,39.425 29.428,39.425 ccw(c29.428,38.775) 28.778,38.775 28.778,33.66 cw(c27.668,33.66) 28.453,32.875 cw(c27.005,34.324) 27.005,32.275 26.628,32.275 24.73,32.275 cw(c24.73,34.815) 22.934,33.019 20.603,35.35 20.372,35.581 cw(c22.168,37.377) 19.628,37.377 19.628,37.45 19.628,38.65 ccw(c19.053,38.65) 19.053,39.225 17.803,39.225
L2 on Top Layer "Top Layer-L2" (solid, remove dead copper, pour order 1022): 34.959,39.428 34.359,39.428 34.081,39.428 ccw(c34.081,38.975) 33.628,38.975 33.628,33.416 ccw(c36.168,33.416) 34.372,31.62 35.592,30.4 36.759,29.232 cw(c34.963,27.436) 37.503,27.436 37.503,23.85 37.503,16.754 ccw(c38.878,16.754) 38.878,15.379 40.457,15.379 ccw(c40.457,16.525) 41.603,16.525 41.603,29.178 ccw(c39.425,29.178) 40.965,30.718 39.059,32.625 36.903,34.781 cw(c38.699,36.577) 36.159,36.577 36.159,37.2 36.159,39.225 ccw(c35.959,39.225) 35.959,39.425 35.059,39.425
VBUS1 on Top Layer "Top Layer-VBUS1 1" (solid, remove dead copper, pour order 1021): 40.344,39.264 39.607,39.264 ccw(c39.607,38.126) 38.469,38.126 38.469,37.569 38.469,36.922 ccw(c39.387,36.922) 39.387,36.004 43.641,36.004 cw(c43.641,34.904) 44.419,35.682 45.239,34.861 ccw(c46.209,35.831) 46.209,34.459 48.411,34.459 ccw(c48.411,35.509) 49.46,35.509 49.46,37.937 ccw(c48.134,37.937) 48.134,39.264 40.344,39.264
VDD on Top Layer "Top Layer-VDD" (solid, remove dead copper, pour order 1020): 46.102,15.543 45.51,15.543 ccw(c45.51,15.273) 45.24,15.273 45.24,6.532 ccw(c45.541,6.532) 45.541,6.231 46.548,6.231 cw(c46.548,5.724) 46.906,6.083 46.996,5.993 cw(c46.3,5.297) 47.285,5.297 47.285,4.462 cw(c46.462,4.462) 47.044,3.88 46.844,3.681 cw(c46.109,4.416) 46.109,3.376 45.533,3.376 ccw(c45.533,2.473) 44.894,3.111 ccw(c45.302,2.703) 44.725,2.703 44.725,1.038 44.725,0.892 ccw(c45.114,0.892) 45.114,0.503 45.94,0.503 ccw(c45.94,0.892) 46.329,0.892 46.329,1.282 cw(c48.32,1.282) 46.912,2.69 48.293,4.07 ccw(c47.894,4.469) 48.458,4.469 48.458,5.591 cw(c49.619,5.591) 48.798,6.413 cw(c49.668,5.542) 49.668,6.773 51.175,6.773 51.303,6.773 ccw(c51.303,7.019) 51.549,7.019 51.549,7.329 ccw(c51.336,7.329) 51.336,7.543 48.177,7.543 47.629,7.543 cw(c47.629,8.043) 47.128,8.043 47.128,15.196 ccw(c46.781,15.196) 46.781,15.543 46.102,15.543
ST on Top Layer "Top Layer-ST" (solid, remove dead copper, pour order 1019): 46.074,20.497 45.426,20.497 ccw(c45.426,20.292) 45.221,20.292 45.221,17.148 ccw(c45.433,17.148) 45.433,16.937 46.904,16.936 46.946,16.936 ccw(c46.946,17.115) 47.125,17.115 47.125,20.304 ccw(c46.932,20.304) 46.932,20.497 46.074,20.497 ccw(c46.074,20.497) 46.074,20.497
VBUS on Top Layer "Top Layer-VBUS 4" (solid, remove dead copper, pour order 1018): 53.23,39.425 52.214,39.425 51.997,39.425 ccw(c51.997,38.203) 50.775,38.203 50.775,35.013 50.775,33.661 cw(c49.593,33.661) 50.429,32.825 45.931,28.327 ccw(c47.727,26.531) 45.187,26.531 45.187,23.56 45.187,22.263 ccw(c45.489,22.263) 45.489,21.961 46.638,21.961 cw(c46.638,21.943) 46.656,21.943 ccw(c46.656,22.421) 47.133,22.421 47.133,22.58 47.133,23.865 cw(c48.34,23.865) 47.486,24.718 cw(c48.18,24.024) 48.18,25.006 48.659,25.006 ccw(c48.659,26.155) 49.471,25.342 49.554,25.425 49.579,25.45 ccw(c47.783,27.246) 50.323,27.246 50.323,27.825 cw(c52.218,27.825) 50.878,29.165 52.059,30.346 53.602,31.89 cw(c54.529,30.963) 54.529,32.273 55.793,32.273 ccw(c55.793,33.334) 56.853,33.334 56.853,37.985 ccw(c55.413,37.985) 55.413,39.425 53.242,39.425
N1 on Top Layer "Top Layer-N1" (hatched Horizontal grid 0.1 track 0.203, pour order 1017): 32.479,31.025
VBUS1 on Top Layer "Top Layer-VBUS1" (hatched Horizontal grid 0.1 track 0.203, pour order 1016): 49.135,36.007
VDS on Top Layer "Top Layer-VDS 1" (hatched Horizontal grid 0.1 track 0.203, pour order 1015): 58.819,28.829 61.862,28.829 62.052,29.019 62.052,30.64 61.878,30.814 58.752,30.814 58.752,28.862
VDS on Top Layer "Top Layer-VDS" (hatched 90Degree grid 0.508 track 0.203, pour order 1007): 216.309,1.226
VBUS on Top Layer "Top Layer-VBUS 3" (hatched 90Degree grid 0.508 track 0.203, remove dead copper, pour order 1003): 53.635,39.183
VBUS on Top Layer "Top Layer-VBUS 2" (hatched 90Degree grid 0.508 track 0.203, remove dead copper, pour order 1002): 53.81,39.414
VBUS on Top Layer "Top Layer-VBUS 1" (hatched 90Degree grid 0.508 track 0.203, remove dead copper, pour order 1001): 55.188,39.183
VBUS on Top Layer "Top Layer-VBUS" (hatched 90Degree grid 0.2 track 0.3, remove dead copper, pour order 1000): 53.771,39.86
TS on Top Layer "Top Layer-No Net" (solid, remove dead copper, pour order 1000): 98.803,38.45 97.553,38.45 ccw(c97.553,36.625) 95.728,36.625 95.728,30.6 ccw(c96.803,30.6) 96.803,29.525 98.778,29.525 ccw(c98.778,31.05) 100.303,31.05 100.303,32.35 cw(c101.728,32.35) 101.728,33.775 115.306,33.775 ccw(c115.306,36.315) 117.102,34.519 118.258,35.675 cw(c119.284,34.649) 119.284,36.1 120.403,36.1 120.778,36.1 ccw(c120.778,36.625) 121.303,36.625 121.303,37.85 ccw(c120.703,37.85) 120.703,38.45 98.803,38.45
VOUT on Top Layer "Top Layer-No Net" (solid, remove dead copper, pour order 1001): 108.978,31.657 103.085,31.657 ccw(c103.085,30.525) 101.953,30.525 101.953,27.325 ccw(c102.903,27.325) 102.903,26.375 107.028,26.375 cw(c107.028,25.15) 108.253,25.15 108.253,5.75 ccw(c109.253,5.75) 109.253,4.75 111.928,4.75 cw(c111.928,4.725) 111.953,4.725 ccw(c111.953,5.337) 112.565,5.337 112.565,5.475 112.565,11.787 cw(c113.628,11.787) 113.628,12.85 115.853,12.85 ccw(c115.853,13.425) 116.428,13.425 116.428,16.3 ccw(c115.503,16.3) 115.503,17.225 112.003,17.225 ccw(c112.003,16.275) 111.053,16.275 111.053,9.83 cw(c110.906,9.83) 111.01,9.725 cw(c110.888,9.847) 110.888,9.675 110.778,9.675 cw(c110.778,9.853) 110.652,9.727 110.629,9.75 cw(c110.814,9.935) 110.553,9.935 110.553,10.025 110.553,16.453 cw(c113.093,16.453) 111.297,18.249 111.74,18.693 ccw(c110.684,19.749) 112.178,19.749 112.178,21.85 112.178,23.925 cw(c113.303,23.925) 113.303,25.05 120.578,25.05 ccw(c120.578,26.025) 121.553,26.025 121.553,28 ccw(c120.628,28) 120.628,28.925 117.903,28.925 cw(c117.903,30.125) 116.703,30.125 ccw(c115.171,30.125) 115.171,31.657 108.978,31.657
TS1 on Top Layer "Top Layer-No Net" (solid, remove dead copper, pour order 1002): 119.603,34.55 118.967,34.55 ccw(c118.967,33.611) 118.303,34.275 117.664,33.636 ccw(c119.201,32.1) 117.028,32.1 117.028,30.95 ccw(c117.253,30.95) 117.253,30.725 120.928,30.725 ccw(c120.928,30.95) 121.153,30.95 121.153,34.1 ccw(c120.703,34.1) 120.703,34.55 119.603,34.55
GND on Top Layer "Top Layer-No Net" (solid, remove dead copper, pour order 1003): 103.653,24.425 101.803,24.425 ccw(c101.803,23.575) 100.953,23.575 100.953,20.05 cw(c99.628,20.05) 99.628,18.725 96.628,18.725 ccw(c96.628,17.975) 95.878,17.975 95.878,15.325 ccw(c96.603,15.325) 96.603,14.6 100.903,14.6 cw(c100.903,13.625) 101.878,13.625 101.878,6.15 cw(c100.153,6.15) 100.153,4.425 88.678,4.425 ccw(c88.678,3.625) 87.878,3.625 87.878,2.025 ccw(c88.528,2.025) 88.528,1.375 115.053,1.375 ccw(c115.053,3.05) 116.728,3.05 116.728,8.175 ccw(c115.628,8.175) 115.628,9.275 114.553,9.275 ccw(c114.553,8.55) 113.828,8.55 113.828,4.6 cw(c112.753,4.6) 112.753,3.525 108.833,3.525 cw(c108.833,5.5) 106.858,5.5 106.858,23.47 ccw(c105.903,23.47) 105.903,24.425 103.653,24.425
LED+ on Top Layer "Top Layer-No Net" (solid, remove dead copper, pour order 1004): 119.803,21.469 118.772,21.469 ccw(c118.772,20.75) 118.053,20.75 118.053,13.975 ccw(c118.953,13.975) 118.953,13.075 121.228,13.075 ccw(c121.228,13.975) 122.128,13.975 122.128,20.194 ccw(c120.853,20.194) 120.853,21.469 119.503,21.469
LED- on Top Layer "Top Layer-No Net" (solid, remove dead copper, pour order 1005): 120.078,9.27 118.923,9.27 ccw(c118.923,8.325) 117.978,8.325 117.978,1.775 ccw(c118.853,1.775) 118.853,0.9 121.191,0.9 ccw(c121.191,1.862) 122.153,1.862 122.153,3.625 122.153,8.645 ccw(c121.528,8.645) 121.528,9.27 120.078,9.27
VOUT on Bottom Layer "Top Layer-No Net" (solid, remove dead copper, pour order 1019): 110.978,31.625 103.053,31.625 ccw(c103.053,30.525) 101.953,30.525 101.953,27.65 ccw(c103.078,27.65) 103.078,26.525 106.998,26.525 cw(c106.998,25.175) 108.348,25.175 108.348,5.43 ccw(c109.003,5.43) 109.003,4.775 111.978,4.775 cw(c111.978,4.75) 112.003,4.75 ccw(c112.003,5.425) 112.678,5.425 112.678,7.025 112.678,11.875 cw(c113.678,11.875) 113.678,12.875 115.778,12.875 ccw(c115.778,13.55) 116.453,13.55 116.453,16.575 ccw(c115.628,16.575) 115.628,17.4 112.234,17.4 ccw(c112.234,16.325) 111.159,16.325 111.159,9.854 cw(c110.917,9.854) 110.917,9.612 110.891,9.612 cw(c110.891,9.75) 110.753,9.75 110.753,16.595 cw(c113.058,16.595) 111.428,18.225 111.484,18.281 ccw(c109.688,20.077) 112.228,20.077 112.228,21.9 112.228,24.225 cw(c113.078,24.225) 113.078,25.075 115.828,25.075 ccw(c115.828,26.325) 117.078,26.325 117.078,31.05 ccw(c116.503,31.05) 116.503,31.625 110.978,31.625
TS on Bottom Layer "Top Layer-No Net" (solid, remove dead copper, pour order 1018): 101.053,38.475 97.628,38.475 ccw(c97.628,36.575) 95.728,36.575 95.728,30.6 ccw(c96.778,30.6) 96.778,29.55 98.803,29.55 ccw(c98.803,31.125) 100.378,31.125 100.378,32.525 cw(c101.628,32.525) 101.628,33.775 116.528,33.775 ccw(c116.528,34.875) 117.628,34.875 117.628,38.25 ccw(c117.403,38.25) 117.403,38.475 101.153,38.475
GND on Bottom Layer "Top Layer-No Net" (solid, remove dead copper, pour order 1017): 89.978,38.008 89.474,38.008 ccw(c89.474,36.937) 88.403,36.937 88.403,32.1 88.403,21.652 ccw(c90.943,21.652) 89.147,19.856 91.278,17.725 95.152,13.851 cw(c93.701,12.4) 95.753,12.4 95.753,9.68 cw(c93.448,9.68) 95.078,8.05 cw(c93.509,9.619) 93.509,7.4 91.203,7.4 89.402,7.4 ccw(c89.402,6.1) 88.102,6.1 88.102,2.526 ccw(c89.103,2.526) 89.103,1.525 114.925,1.525 ccw(c114.925,3.2) 116.6,3.2 116.6,8.442 ccw(c116.103,8.442) 116.103,8.94 114.418,8.94 ccw(c114.418,8.525) 114.004,8.525 114.004,4.601 cw(c112.828,4.601) 112.828,3.425 107.703,3.425 cw(c107.703,4.175) 106.953,4.175 106.953,23.7 ccw(c106.428,23.7) 106.428,24.225 101.653,24.225 ccw(c101.653,23.475) 100.903,23.475 100.903,21.79 cw(c98.363,21.79) 98.363,19.25 97.028,19.25 94.568,19.25 cw(c94.568,21.79) 92.028,21.79 92.028,23.5 92.028,37.575 ccw(c91.603,37.575) 91.603,38 90.011,38 cw(c90.011,38.008) 90.003,38.008
cs on Bottom Layer "Top Layer-No Net" (solid, remove dead copper, pour order 1016): 61.478,21.05 59.978,21.05 ccw(c59.978,20.55) 59.478,20.55 59.478,18.55 ccw(c59.953,18.55) 59.953,18.075 63.053,18.075 ccw(c63.053,18.5) 63.478,18.5 63.478,20.3 ccw(c62.728,20.3) 62.728,21.05 61.478,21.05
G on Bottom Layer "Top Layer-No Net" (solid, remove dead copper, pour order 1015): 60.603,27.325 59.428,27.325 ccw(c59.428,27) 59.103,27 59.103,24.925 ccw(c59.503,24.925) 59.503,24.525 62.853,24.525 ccw(c62.853,24.95) 63.278,24.95 63.278,26.925 ccw(c62.878,26.925) 62.878,27.325 60.603,27.325
VDS on Bottom Layer "Top Layer-No Net" (solid, remove dead copper, pour order 1014): 63.553,30.925 61.103,30.925 ccw(c61.103,30.525) 60.703,30.525 60.703,29.175 ccw(c61.153,29.175) 61.153,28.725 64.778,28.725 cw(c64.778,27.85) 65.653,27.85 65.653,24.425 cw(c64.753,24.425) 64.753,23.525 60.236,23.525 ccw(c60.236,23.125) 59.836,23.125 59.836,22.457 ccw(c60.293,22.457) 60.293,22 60.503,22 74.353,22 ccw(c74.353,22.7) 75.053,22.7 75.053,24.875 ccw(c74.378,24.875) 74.378,25.55 67.878,25.55 cw(c67.878,26.525) 66.903,26.525 66.903,30.45 ccw(c66.428,30.45) 66.428,30.925 63.553,30.925
VBUS on Bottom Layer "Top Layer-No Net" (solid, remove dead copper, pour order 1013): 53.328,39.15 51.403,39.15 ccw(c51.403,38.625) 50.878,38.625 50.878,37.1 50.878,35.177 cw(c48.338,35.177) 50.134,33.381 49.653,32.9 47.829,31.076 ccw(c48.554,30.35) 47.528,30.35 47.528,27.3 47.528,25.927 ccw(c48.539,25.927) 48.539,24.917 49.517,24.917 ccw(c49.517,27.457) 51.314,25.661 54.078,28.425 57.922,32.269 cw(c59.719,30.473) 59.719,33.013 62.528,33.013 68.015,33.013 cw(c68.015,31.85) 69.178,31.85 69.178,30.475 ccw(c70.128,30.475) 70.128,29.525 79.353,29.525 ccw(c79.353,30.975) 80.803,30.975 80.803,36.783 ccw(c79.478,36.783) 79.478,38.108 65.936,38.108 ccw(c65.936,37.35) 65.178,37.35 65.178,35.8 cw(c64.303,35.8) 64.303,34.925 57.955,34.925 ccw(c57.955,32.385) 56.159,34.181 53.803,31.825 50.174,28.196 cw(c50.003,28.366) 50.003,28.125 cw(c50.003,28.306) 49.875,28.178 49.828,28.225 cw(c50.009,28.406) 49.753,28.406 49.753,28.525 cw(c49.916,28.525) 49.801,28.64 50.11,28.95 55.009,33.849 ccw(c53.213,35.645) 55.753,35.645 55.753,36.025 55.753,38.375 ccw(c54.978,38.375) 54.978,39.15 53.328,39.15
VDD on Bottom Layer "Top Layer-No Net" (solid, remove dead copper, pour order 1012): 45.803,8.175 45.528,8.175 ccw(c45.528,7.8) 45.153,7.8 45.153,6.725 ccw(c45.628,6.725) 45.628,6.25 46.678,6.25 ccw(c46.678,6.55) 46.978,6.55 46.978,7.8 ccw(c46.603,7.8) 46.603,8.175 45.803,8.175
TA on Bottom Layer "Top Layer-No Net" (solid, remove dead copper, pour order 1011): 72.453,9.923 69.927,9.923 ccw(c69.927,8.95) 68.953,8.95 68.953,7.499 cw(c66.905,7.499) 68.353,6.05 cw(c66.663,7.74) 66.663,5.35 62.278,5.35 61.305,5.35 ccw(c61.305,2.81) 59.509,4.606 59.078,4.175 58.997,4.094 cw(c57.201,5.89) 57.201,3.35 56.553,3.35 56.128,3.35 ccw(c56.128,2.475) 55.253,2.475 55.253,1.275 ccw(c55.853,1.275) 55.853,0.675 72.815,0.675 ccw(c72.815,2.55) 74.69,2.55 74.69,9.413 ccw(c74.178,9.413) 74.178,9.925 72.53,9.925 ccw(c72.53,9.923) 72.528,9.923
GNDE on Bottom Layer "Top Layer-No Net" (solid, remove dead copper, pour order 1010): 25.078,39.089 24.322,39.089 ccw(c24.322,38.425) 23.659,38.425 23.659,35.527 ccw(c26.199,35.527) 24.403,33.731 24.759,33.375 24.812,33.321 ccw(c26.608,35.117) 26.608,32.577 28.878,32.577 39.848,32.577 cw(c39.848,30.037) 41.645,31.834 43.403,30.075 cw(c42.496,29.168) 43.779,29.168 43.779,25.6 43.779,14.751 ccw(c46.319,14.751) 44.523,12.955 46.778,10.7 48.571,8.907 cw(c47.59,7.925) 48.978,7.925 48.978,6.77 cw(c47.783,6.77) 48.628,5.925 cw(c47.904,6.649) 47.904,5.625 46.653,5.625 45.878,5.625 ccw(c45.878,4.85) 45.103,4.85 45.103,3.675 ccw(c45.753,3.675) 45.753,3.025 53.076,3.025 ccw(c53.076,5.565) 54.872,3.769 55.328,4.225 56.834,5.731 cw(c58.63,3.935) 58.63,6.475 58.759,6.475 64.153,6.475 ccw(c64.153,7.25) 64.928,7.25 64.928,8.9 ccw(c64.303,8.9) 64.303,9.525 59.48,9.525 ccw(c59.48,6.985) 57.684,8.781 54.603,5.7 cw(c53.034,7.269) 53.034,5.05 52.278,5.05 50.849,5.05 cw(c50.849,5.221) 50.728,5.1 cw(c50.788,5.16) 50.703,5.16 50.703,5.175 cw(c50.763,5.175) 50.721,5.218 50.728,5.225 50.976,5.473 ccw(c50.61,5.84) 51.128,5.84 51.128,8.025 51.128,9.259 cw(c51.469,9.259) 51.228,9.5 cw(c51.288,9.44) 51.288,9.525 51.359,9.525 cw(c51.359,9.465) 51.401,9.507 51.459,9.45 cw(c51.217,9.209) 51.559,9.209 51.559,9.108 51.592,9.074 ccw(c52.978,10.46) 52.978,8.5 53.974,8.5 ccw(c53.974,11.04) 55.77,9.244 56.592,10.066 56.645,10.12 cw(c58.441,8.324) 58.441,10.864 66.128,10.864 ccw(c66.128,12.345) 67.176,11.298 68.753,12.875 cw(c70.021,11.608) 70.021,13.4 75.103,13.4 75.176,13.4 cw(c75.176,10.86) 76.972,12.656 77.278,12.35 cw(c76.118,11.19) 77.758,11.19 77.758,7.125 77.758,2.872 ccw(c78.903,2.872) 78.903,1.728 79.931,1.728 ccw(c79.931,2.85) 81.053,2.85 81.053,15.885 ccw(c78.513,15.885) 78.513,18.425 76.753,18.425 70.03,18.425 ccw(c70.03,15.885) 68.234,17.681 67.028,16.475 66.547,15.994 cw(c64.751,17.79) 64.751,15.25 62.128,15.25 59.755,15.25 cw(c59.755,17.79) 57.959,15.994 55.853,18.1 ccw(c54.223,16.47) 54.223,18.775 52.259,18.775 ccw(c52.259,17.856) 51.609,18.506 49.728,16.625 49.392,16.289 cw(c47.728,17.954) 47.728,15.6 47.696,15.6 cw(c47.696,17.392) 46.428,16.125 cw(c47.492,17.189) 45.987,17.189 45.987,22.225 45.987,30.269 ccw(c43.447,30.269) 45.244,32.065 44.159,33.15 43.797,33.512 ccw(c42.001,31.716) 42.001,34.256 39.603,34.256 27.878,34.256 cw(c27.878,35.775) 26.359,35.775 26.359,38.633 ccw(c25.903,38.633) 25.903,39.089 25.078,39.089
VBUS1 on Bottom Layer "Top Layer-No Net" (solid, remove dead copper, pour order 1009): 40.753,39.275 39.553,39.275 ccw(c39.553,38.5) 38.778,38.5 38.778,36.85 ccw(c39.553,36.85) 39.553,36.075 43.371,36.075 cw(c43.371,34.368) 44.578,35.575 45.314,34.839 ccw(c46.253,35.778) 46.253,34.45 48.403,34.45 ccw(c48.403,35.55) 49.503,35.55 49.503,38.425 ccw(c48.653,38.425) 48.653,39.275 40.753,39.275
L2 on Bottom Layer "Top Layer-No Net" (solid, remove dead copper, pour order 1008): 39.303,30.675 ccw(c39.303,28.875) 37.503,28.875 37.503,28.55 37.503,16.575 ccw(c38.678,16.575) 38.678,15.4 40.503,15.4 ccw(c40.503,16.5) 41.603,16.5 41.603,29.1 ccw(c40.028,29.1) 40.028,30.675 39.303,30.675
L2 on Bottom Layer "Top Layer-No Net" (solid, remove dead copper, pour order 1007): 35.03,39.494 34.28,39.494 ccw(c34.28,38.944) 33.73,38.944 33.73,36.619 ccw(c34.03,36.619) 34.03,36.319 35.98,36.319 ccw(c35.98,36.544) 36.205,36.544 36.205,39.144 ccw(c35.855,39.144) 35.855,39.494 35.03,39.494
N1 on Bottom Layer "Top Layer-No Net" (solid, remove dead copper, pour order 1006): 30.053,39.475 29.303,39.475 ccw(c29.303,38.925) 28.753,38.925 28.753,36.6 ccw(c29.053,36.6) 29.053,36.3 31.003,36.3 ccw(c31.003,36.525) 31.228,36.525 31.228,39.125 ccw(c30.878,39.125) 30.878,39.475 30.053,39.475
N4 on Bottom Layer "Top Layer-No Net" (solid, remove dead copper, pour order 1005): 32.053,23.975 29.278,23.975 ccw(c29.278,23.525) 28.828,23.525 28.828,21.975 ccw(c29.353,21.975) 29.353,21.45 33.003,21.45 ccw(c33.003,21.9) 33.453,21.9 33.453,23.45 ccw(c32.928,23.45) 32.928,23.975 32.053,23.975
N1 on Bottom Layer "Top Layer-No Net" (solid, remove dead copper, pour order 1004): 17.803,39 16.928,39 ccw(c16.928,38.35) 16.278,38.35 16.278,37.902 ccw(c18.818,37.902) 17.022,36.106 17.878,35.25 24.659,28.469 cw(c22.863,26.673) 25.403,26.673 25.403,25.65 25.403,16.6 ccw(c26.452,16.6) 26.452,15.551 26.903,15.551 27.279,15.551 ccw(c27.279,16.625) 28.353,16.625 28.353,17.823 ccw(c27.055,17.823) 27.973,18.74 cw(c28.806,19.573) 27.628,19.573 27.628,20 27.628,25.416 cw(c29.762,25.416) 28.253,26.925 cw(c29.776,25.402) 29.776,27.556 30.259,27.556 ccw(c30.259,28.325) 31.028,28.325 31.028,29.25 31.028,30.201 ccw(c30.303,30.201) 30.303,30.926 25.279,30.926 cw(c25.279,33.466) 23.483,31.67 23.353,31.8 20.372,34.781 cw(c22.168,36.577) 19.628,36.577 19.628,37.975 ccw(c18.603,37.975) 18.603,39 18.503,39 17.803,39
L1 on Bottom Layer "Top Layer-No Net" (solid, remove dead copper, pour order 1003): 17.928,32.5 17.162,32.5 ccw(c17.162,32) 16.662,32 16.662,25.566 ccw(c17.553,25.566) 17.553,24.675 19.351,24.675 cw(c19.351,22.135) 21.147,23.931 21.803,23.275 cw(c20.157,21.629) 22.485,21.629 22.485,20.525 22.485,15.456 ccw(c25.025,15.456) 23.229,13.66 24.387,12.502 25.17,11.719 ccw(c26.966,13.515) 26.966,10.975 32.728,10.975 34.676,10.975 cw(c34.676,8.435) 36.472,10.231 36.928,9.775 cw(c36.023,8.87) 37.303,8.87 37.303,7.325 37.303,5.702 cw(c34.763,5.702) 36.559,3.906 36.203,3.55 36.122,3.469 cw(c34.326,5.265) 34.326,2.725 33.728,2.725 23.13,2.725 cw(c23.13,5.265) 21.334,3.469 21.103,3.7 ccw(c19.473,2.07) 19.473,4.375 19.253,4.375 14.278,4.375 ccw(c14.278,3.425) 13.328,3.425 13.328,1.4 ccw(c14.178,1.4) 14.178,0.55 38.446,0.55 ccw(c38.446,3.09) 40.986,3.09 40.986,3.15 40.986,8.84 ccw(c38.446,8.84) 40.242,10.636 39.053,11.825 38.922,11.956 ccw(c37.126,10.16) 37.126,12.7 35.178,12.7 27.23,12.7 cw(c27.23,15.24) 25.434,13.444 24.153,14.725 cw(c25.36,15.932) 23.653,15.932 23.653,21.025 23.653,23.323 ccw(c21.113,23.323) 22.909,25.119 19.803,28.225 cw(c20.648,29.07) 19.453,29.07 19.453,30.85 19.453,30.975 ccw(c17.928,30.975) 17.928,32.5
N on Bottom Layer "Top Layer-No Net" (solid, remove dead copper, pour order 1002): 18.403,22.593 17.971,22.593 ccw(c17.971,21.825) 17.203,21.825 17.203,18.602 cw(c14.663,18.602) 16.459,16.806 16.203,16.55 14.107,14.454 ccw(c15.903,12.658) 13.363,12.658 13.363,12.5 13.363,10.44 ccw(c13.803,10.44) 13.803,10 16.003,10 ccw(c16.003,10.725) 16.728,10.725 16.728,12.517 cw(c19.268,12.517) 17.472,14.313 18.859,15.7 cw(c19.341,15.217) 19.341,15.9 19.359,15.9 cw(c19.359,15.659) 19.529,15.829 19.559,15.8 cw(c19.419,15.661) 19.616,15.661 19.616,15.475 cw(c19.212,15.475) 19.498,15.189 19.459,15.15 ccw(c20.86,13.748) 18.878,13.748 18.878,12.05 18.878,11.227 ccw(c21.418,11.227) 19.622,9.431 23.328,5.725 23.359,5.694 ccw(c25.155,7.49) 25.155,4.95 26.278,4.95 28.128,4.95 ccw(c28.128,5.65) 28.828,5.65 28.828,7.65 ccw(c28.103,7.65) 28.103,8.375 26.28,8.375 cw(c26.28,10.915) 24.484,9.119 24.178,9.425 21.407,12.196 cw(c23.203,13.992) 20.663,13.992 20.663,19.95 20.663,21.089 ccw(c19.159,21.089) 19.159,22.593 18.403,22.593
HV1 on Bottom Layer "Bottom Layer-HV1" (hatched Horizontal grid 0.1 track 0.203, pour order 1077): 61.936,39.158 59.24,39.158 59.067,38.984 59.067,36.77 59.212,36.625 61.969,36.625 62.184,36.84 62.184,38.91 61.969,39.125
TS on Bottom Layer "Bottom Layer-TS 2" (hatched Horizontal grid 0.1 track 0.203, pour order 1067): 94.834,35.66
